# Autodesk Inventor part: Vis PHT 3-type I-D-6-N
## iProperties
Created: 2011-01
Part Number: Vis PHT 3-type I-D-6-N
Document SubType Name: Modeling
Designer: eric
Density: 1 g/cm^3
Mass: 0.0840367 g
Surface Area: 1.53 cm^2
Volume: 0.0840367 cm^3
Author: eric
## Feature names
1. Base1
